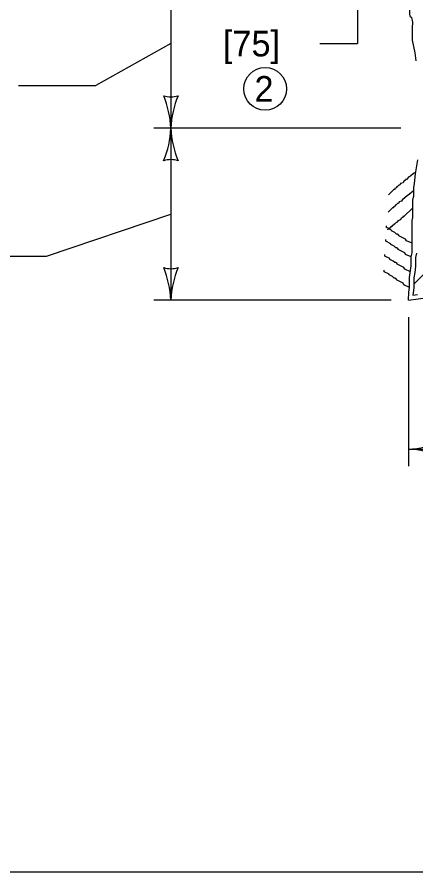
# Model space of a CAD drawing. Extents: x 49991.4 to 50021, y 49987.6 to 50011.4.
# Drawn here: x 50010.938 to 50011.871, y 49999.886 to 50001.886 of the extents above; entities that cross this region are included whole.
import ezdxf

# ---------------------------------------------------------------- set-up
doc = ezdxf.new("R2010")
doc.units = 0
for name, color, linetype in [('Level 1', 7, 'Continuous'), ('Level 2', 7, 'Continuous'), ('Level 3', 7, 'Continuous')]:
    doc.layers.add(name, color=color, linetype=linetype)

msp = doc.modelspace()

# ---------------------------------------------------------------- linework, layer by layer
at = {"layer": 'Level 1'}
msp.add_line((50011.8662, 50001.2608), (50012.2465, 50001.641), dxfattribs=at)
msp.add_lwpolyline([(50020.9378, 50008.1646), (50009.7374, 50008.1646), (50009.7374, 49999.8856), (50020.9378, 49999.8856)], close=True, dxfattribs=at)
for points in [[(50011.8578, 50001.8856), (50011.8568, 50001.8926), (50011.8568, 50001.8926), (50011.857, 50001.939), (50011.8562, 50001.9987), (50011.8562, 50002.0295), (50011.8581, 50002.0373), (50011.8581, 50002.0527), (50011.86, 50002.0797), (50011.8639, 50002.1009), (50011.8639, 50002.1163), (50011.8658, 50002.1201)], [(50011.8711, 50001.7838), (50011.869, 50001.8022), (50011.8627, 50001.8322), (50011.863, 50001.861), (50011.8634, 50001.8744), (50011.861, 50001.885), (50011.8578, 50001.8856)], [(50011.8533, 50001.2238), (50011.8543, 50001.242), (50011.8562, 50001.2535), (50011.8562, 50001.2766), (50011.86, 50001.3037), (50011.86, 50001.3248), (50011.862, 50001.3345), (50011.862, 50001.3788), (50011.862, 50001.4097), (50011.8639, 50001.4174), (50011.8639, 50001.4579), (50011.8658, 50001.4675), (50011.8658, 50001.4868), (50011.8677, 50001.4965), (50011.8697, 50001.5196), (50011.8755, 50001.5523)], [(50011.8697, 50001.5196), (50011.8677, 50001.5215), (50011.86, 50001.5157), (50011.8581, 50001.5157), (50011.8581, 50001.5138), (50011.8542, 50001.5119), (50011.8485, 50001.5061), (50011.8465, 50001.5061), (50011.8465, 50001.5042), (50011.8427, 50001.5022), (50011.8408, 50001.4984), (50011.8349, 50001.4964), (50011.833, 50001.4926), (50011.8311, 50001.4926), (50011.8272, 50001.4888), (50011.8253, 50001.4888), (50011.8253, 50001.4868), (50011.8215, 50001.4849), (50011.8215, 50001.4829), (50011.8195, 50001.4829), (50011.8067, 50001.4701)], [(50011.8658, 50001.4772), (50011.8645, 50001.4785), (50011.8567, 50001.4727), (50011.8548, 50001.4727), (50011.8548, 50001.4708), (50011.8509, 50001.4689), (50011.8452, 50001.4631), (50011.8433, 50001.4631), (50011.8433, 50001.4612), (50011.8394, 50001.4593), (50011.8374, 50001.4554), (50011.8317, 50001.4535), (50011.8298, 50001.4496), (50011.8278, 50001.4496), (50011.824, 50001.4457), (50011.8221, 50001.4457), (50011.8221, 50001.4438), (50011.8182, 50001.4419), (50011.8182, 50001.44), (50011.8162, 50001.44), (50011.806, 50001.4294)], [(50011.8625, 50001.439), (50011.8422, 50001.419), (50011.8403, 50001.419), (50011.8403, 50001.4171), (50011.8365, 50001.4151), (50011.8345, 50001.4113), (50011.8287, 50001.4093), (50011.8268, 50001.4055), (50011.8249, 50001.4055), (50011.821, 50001.4016), (50011.8191, 50001.4016), (50011.8191, 50001.3997), (50011.8153, 50001.3978), (50011.8153, 50001.3959), (50011.8133, 50001.3959), (50011.8095, 50001.392), (50011.8076, 50001.392), (50011.8076, 50001.39), (50011.8036, 50001.3881)], [(50011.862, 50001.3567), (50011.8485, 50001.3625), (50011.8465, 50001.3663), (50011.8311, 50001.374), (50011.8311, 50001.3759), (50011.8273, 50001.3779), (50011.8253, 50001.3779), (50011.8215, 50001.3818), (50011.8138, 50001.3856), (50011.8138, 50001.3875), (50011.8022, 50001.3933), (50011.8022, 50001.3972)], [(50011.86, 50001.3248), (50011.8465, 50001.3306), (50011.8446, 50001.3345), (50011.8292, 50001.3422), (50011.8292, 50001.3441), (50011.8254, 50001.346), (50011.8235, 50001.346), (50011.8196, 50001.3499), (50011.8118, 50001.3538), (50011.8118, 50001.3557), (50011.8003, 50001.3615), (50011.8003, 50001.3653)], [(50011.8581, 50001.2901), (50011.8446, 50001.2959), (50011.8427, 50001.2998), (50011.8272, 50001.3075), (50011.8272, 50001.3095), (50011.8234, 50001.3114), (50011.8215, 50001.3114), (50011.8176, 50001.3152), (50011.8099, 50001.3191), (50011.8099, 50001.321), (50011.7983, 50001.3268), (50011.7983, 50001.3307)], [(50011.872, 50001.3335), (50011.87, 50001.3238), (50011.87, 50001.303), (50011.868, 50001.2887), (50011.8662, 50001.2759), (50011.8662, 50001.2527), (50011.8642, 50001.2409), (50011.8639, 50001.2353), (50011.8747, 50001.2366)], [(50011.8562, 50001.2535), (50011.8427, 50001.2593), (50011.8408, 50001.2632), (50011.8253, 50001.2709), (50011.8253, 50001.2729), (50011.8215, 50001.2747), (50011.8196, 50001.2747), (50011.8157, 50001.2786), (50011.808, 50001.2825), (50011.808, 50001.2844), (50011.7964, 50001.2902), (50011.7964, 50001.294)], [(50011.8533, 50001.2238), (50011.8985, 50001.2296)]]:
    msp.add_lwpolyline(points, dxfattribs=at)
at = {"layer": 'Level 2'}
msp.add_circle((50011.5182, 50001.718), 0.05, dxfattribs=at)
at = {"layer": 'Level 3'}
for p, q in [((50011.2975, 50002.022), (50011.2975, 50001.626)), ((50011.7344, 50001.954), (50011.7344, 50001.824)), ((50011.2975, 50001.824), (50011.1222, 50001.7263)), ((50011.6458, 50001.824), (50011.7344, 50001.824)), ((50010.9407, 50001.7263), (50011.1222, 50001.7263)), ((50011.8355, 50001.626), (50011.2575, 50001.626)), ((50011.2975, 50001.626), (50011.2975, 50001.2238)), ((50011.0068, 50001.3263), (50011.2975, 50001.4249)), ((50010.8208, 50001.3263), (50011.0068, 50001.3263)), ((50011.8133, 50001.2238), (50011.2575, 50001.2238)), ((50011.8533, 50001.1838), (50011.8533, 50000.8348)), ((50011.8533, 50000.8748), (50014.1051, 50000.8748))]:
    msp.add_line(p, q, dxfattribs=at)
for centre, radius, start, end in [((50011.2975, 50001.7542), 0.0548, 252.1388, 287.8612), ((50011.0648, 50001.6145), 0.233, 2.8273, 22.0772), ((50011.5196, 50001.6168), 0.2223, 157.456, 177.6395), ((50011.0753, 50001.6351), 0.2223, 337.456, 357.6395), ((50011.0753, 50001.6351), 0.2223, 337.456, 357.6395), ((50011.5302, 50001.6374), 0.233, 182.8273, 202.0772), ((50011.5302, 50001.6374), 0.233, 182.8273, 202.0772), ((50011.2975, 50001.4977), 0.0548, 72.1388, 107.8612), ((50011.2975, 50001.4977), 0.0548, 72.1388, 107.8612), ((50011.2975, 50001.352), 0.0548, 252.1388, 287.8612), ((50011.0648, 50001.2123), 0.233, 2.8273, 22.0772), ((50011.2975, 50001.352), 0.0548, 252.1388, 287.8612), ((50011.0648, 50001.2123), 0.233, 2.8273, 22.0772), ((50011.5196, 50001.2147), 0.2223, 157.456, 177.6395), ((50011.5196, 50001.2147), 0.2223, 157.456, 177.6395), ((50011.8418, 50001.1075), 0.233, 272.8273, 292.0772), ((50011.8442, 50000.6527), 0.2223, 67.456, 87.6395)]:
    msp.add_arc(centre, radius, start, end, dxfattribs=at)

# ---------------------------------------------------------------- texts
at = {"layer": 'Level 2'}
for s, p in [('[75]', (50011.4192, 50001.794)), ('2', (50011.4931, 50001.688))]:
    msp.add_text(s, height=0.06, dxfattribs=at).set_placement(p)

doc.saveas('drawing.dxf')
